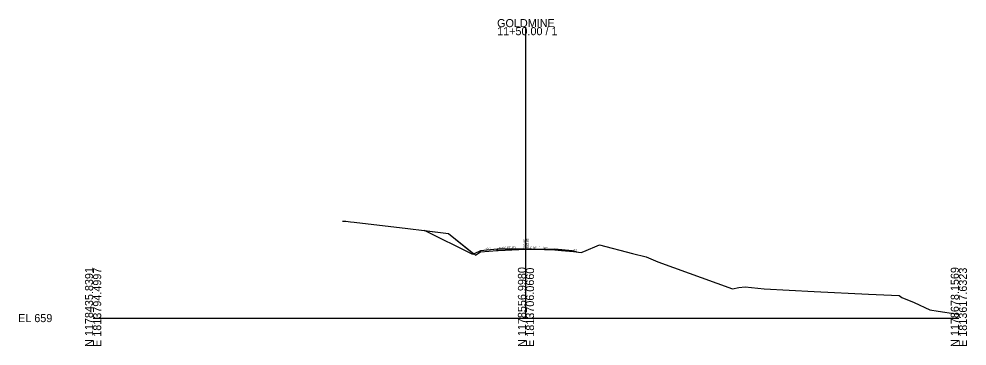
# Model space of a CAD drawing. Extents: x -26 to 1603, y -10 to 1590.
# Drawn here: x 1274.3 to 1602.8, y 990.3 to 1103.7 of the extents above; entities that cross this region are included whole.
import ezdxf

# ---------------------------------------------------------------- set-up
doc = ezdxf.new("R2010")
doc.units = 0
for name, color, linetype in [('Default', 7, 'Continuous'), ('RD_GPK_XS_Cell', 7, 'Continuous'), ('RD_XS_EarthShd', 7, 'Continuous'), ('RD_XS_ExGround', 7, 'Continuous'), ('RD_XS_Misc_Line', 7, 'Continuous'), ('RD_XS_Pave', 7, 'Continuous'), ('RD_XS_TieSlope', 7, 'Continuous'), ('RD_XS_TX_Elev_EX', 7, 'Continuous'), ('RD_XS_TX_Slope', 7, 'Continuous')]:
    doc.layers.add(name, color=color, linetype=linetype)

msp = doc.modelspace()

# ---------------------------------------------------------------- linework, layer by layer
at = {"layer": 'Default'}
for q in [(1440.05, 1023.84), (1459.95, 1023.85)]:
    msp.add_line((1450, 1023.85), q, dxfattribs=at)
at = {"layer": 'RD_GPK_XS_Cell'}
for p, q in [((1450, 1000), (1450, 1100.87)), ((1300, 1000), (1450, 1000)), ((1450, 1000), (1600, 1000))]:
    msp.add_line(p, q, dxfattribs=at)
at = {"layer": 'RD_XS_EarthShd'}
for p, q in [((1440.05, 1023.84), (1434.25, 1023.36)), ((1459.95, 1023.85), (1465.95, 1023.35))]:
    msp.add_line(p, q, dxfattribs=at)
at = {"layer": 'RD_XS_ExGround'}
for p, q in [((1386.47, 1033.62), (1387.54, 1033.58)), ((1387.54, 1033.58), (1389.19, 1033.42)), ((1389.19, 1033.42), (1390.52, 1033.28)), ((1390.52, 1033.28), (1397.26, 1032.47)), ((1397.26, 1032.47), (1408.1, 1031.16)), ((1408.1, 1031.16), (1423.13, 1029.38)), ((1423.13, 1029.38), (1431.05, 1023)), ((1470.05, 1023.08), (1475.46, 1025.35)), ((1475.46, 1025.35), (1486.88, 1022.35)), ((1432, 1022.23), (1432.48, 1021.84)), ((1432.48, 1021.84), (1434.25, 1022.96)), ((1434.25, 1022.96), (1440.05, 1023.47)), ((1440.05, 1023.47), (1440.39, 1023.48)), ((1440.39, 1023.48), (1450, 1023.85)), ((1450, 1023.85), (1450.67, 1023.87)), ((1450.67, 1023.87), (1456.37, 1023.75)), ((1456.37, 1023.75), (1459.95, 1023.66)), ((1459.95, 1023.66), (1462.34, 1023.46)), ((1462.34, 1023.46), (1466.5, 1023.11)), ((1466.5, 1023.11), (1469.14, 1022.7)), ((1469.14, 1022.7), (1470.05, 1023.08)), ((1486.88, 1022.35), (1491.63, 1021.22)), ((1491.63, 1021.22), (1495.65, 1019.52)), ((1495.65, 1019.52), (1521.59, 1010.19)), ((1521.59, 1010.19), (1523.8, 1010.56)), ((1523.8, 1010.56), (1525.98, 1010.88)), ((1525.98, 1010.88), (1532.49, 1010.17)), ((1532.49, 1010.17), (1549.81, 1009.2)), ((1549.81, 1009.2), (1568.74, 1008.24)), ((1568.74, 1008.24), (1579.28, 1007.87)), ((1579.28, 1007.87), (1580.26, 1007.16)), ((1580.26, 1007.16), (1584.53, 1005.42)), ((1584.53, 1005.42), (1589.99, 1002.83)), ((1589.99, 1002.83), (1592.86, 1002.39)), ((1592.86, 1002.39), (1598.93, 1001.46)), ((1598.93, 1001.46), (1599.5, 1001.4)), ((1599.5, 1001.4), (1600, 1001.42))]:
    msp.add_line(p, q, dxfattribs=at)
at = {"layer": 'RD_XS_Misc_Line'}
for points in [[(1431.94, 1022.28), (1432, 1022.23), (1431.53, 1022), (1414.79, 1030.37), (1423.13, 1029.38)], [(1432.48, 1021.84), (1434.25, 1022.96), (1440.05, 1023.47), (1440.05, 1023.84), (1434.25, 1023.36), (1432, 1022.23)], [(1450, 1023.85), (1440.05, 1023.84), (1440.05, 1023.47), (1440.39, 1023.48)], [(1450.67, 1023.87), (1451.81, 1023.85), (1450, 1023.85)], [(1451.81, 1023.85), (1459.95, 1023.85), (1459.95, 1023.66), (1456.37, 1023.75)], [(1459.95, 1023.66), (1462.34, 1023.46), (1466.5, 1023.11), (1467.53, 1022.95), (1465.95, 1023.35), (1459.95, 1023.85)]]:
    msp.add_lwpolyline(points, close=True, dxfattribs=at)
at = {"layer": 'RD_XS_Pave'}
for p, q in [((1440.05, 1023.47), (1440.05, 1023.84)), ((1459.95, 1023.66), (1459.95, 1023.85))]:
    msp.add_line(p, q, dxfattribs=at)
at = {"layer": 'RD_XS_TieSlope'}
msp.add_line((1467.53, 1022.95), (1465.95, 1023.35), dxfattribs=at)

# ---------------------------------------------------------------- texts
at = {"layer": 'Default'}
msp.add_text('682.85', height=0.8, rotation=90, dxfattribs=at).set_placement((1450.91, 1024.25))
at = {"layer": 'RD_GPK_XS_Cell'}
for s, p in [('GOLDMINE', (1440, 1100.87)), ('11+50.00 / 1', (1440, 1098.07)), ('EL 659', (1274, 998.6))]:
    msp.add_text(s, height=2.8, dxfattribs=at).set_placement(p)
for s, p in [('N 1178435.8391', (1300, 990)), ('E 1813794.4997', (1302.8, 990)), ('N 1178556.9980', (1450, 990)), ('E 1813706.0660', (1452.8, 990)), ('N 1178678.1569', (1600, 990)), ('E 1813617.6323', (1602.8, 990))]:
    msp.add_text(s, height=2.8, rotation=90, dxfattribs=at).set_placement(p)
at = {"layer": 'RD_XS_TX_Elev_EX'}
msp.add_text('682.85', height=0.8, rotation=90, dxfattribs=at).set_placement((1450, 1024.01))
at = {"layer": 'RD_XS_TX_Slope'}
for s, rotation, p in [('12:1', 5.8181, (1435.96, 1023.54)), ('0.400 FT./FT.', 1.1916, (1440.59, 1023.92)), ('0.021 FT./FT.', 358.8084, (1451.49, 1024.02)), ('4:1', 346.0758, (1466.29, 1023.29))]:
    msp.add_text(s, height=0.75, rotation=rotation, dxfattribs=at).set_placement(p)

doc.saveas('drawing.dxf')
